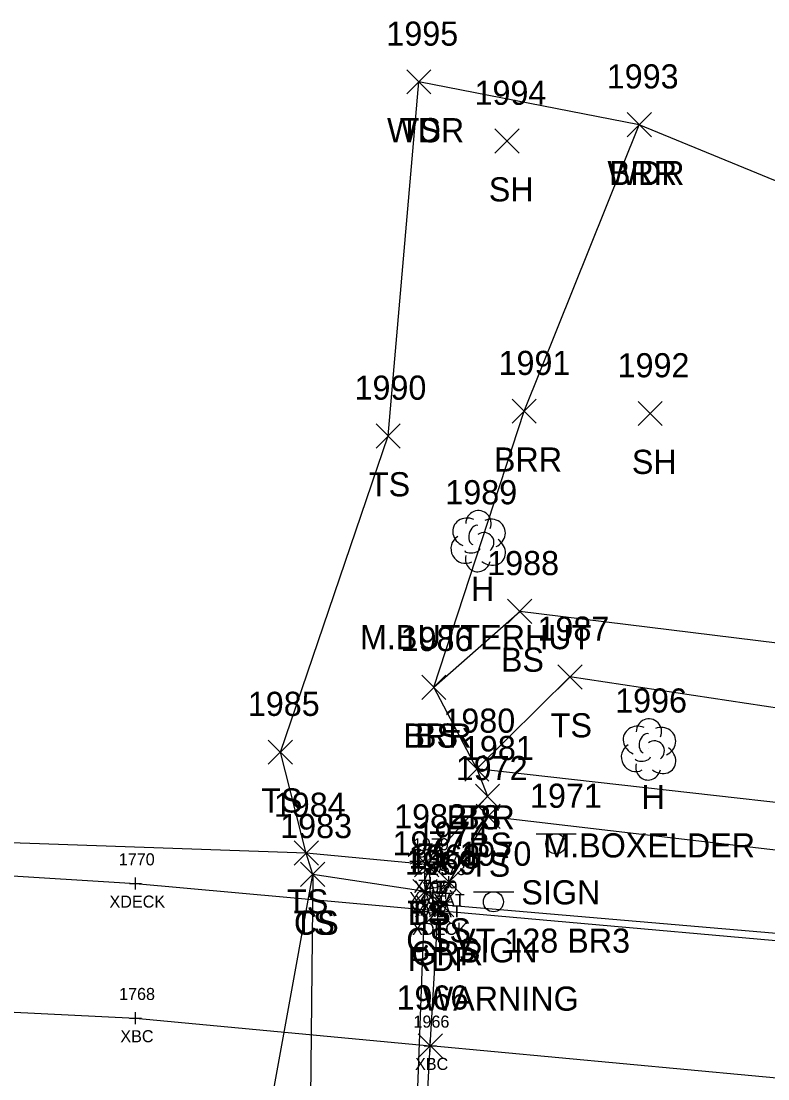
# Model space of a CAD drawing. Extents: x 1497084 to 1499861, y 734741 to 735567.
# Drawn here: x 1499561.5 to 1499623.4, y 735456.1 to 735543.7 of the extents above; entities that cross this region are included whole.
import ezdxf

# ---------------------------------------------------------------- set-up
doc = ezdxf.new("R2010")
doc.units = 0
for name, color, linetype in [('B_A', 7, 'Continuous'), ('B_I', 7, 'Continuous'), ('B_TIC', 7, 'Continuous'), ('BELB', 7, 'Continuous'), ('BSUBM', 7, 'Continuous'), ('L_A', 7, 'Continuous'), ('L_C', 7, 'Continuous'), ('L_I', 7, 'Continuous'), ('L_TIC', 7, 'Continuous'), ('LABL', 7, 'Continuous'), ('LAWA', 7, 'Continuous'), ('LELB', 7, 'Continuous'), ('LTD', 7, 'Continuous'), ('P_A', 7, 'Continuous'), ('P_I', 7, 'Continuous'), ('P_TIC', 7, 'Continuous'), ('PET', 7, 'Continuous'), ('PRC', 7, 'Continuous'), ('R_A', 7, 'Continuous'), ('R_I', 7, 'Continuous'), ('R_TIC', 7, 'Continuous'), ('RGR', 7, 'Continuous'), ('S_A', 7, 'Continuous'), ('S_C', 7, 'Continuous'), ('S_I', 7, 'Continuous'), ('SSGN', 7, 'Continuous')]:
    doc.layers.add(name, color=color, linetype=linetype)

msp = doc.modelspace()

# ---------------------------------------------------------------- linework, layer by layer
at = {"layer": 'B_TIC'}
for p, q in [((1499595.343, 735473.493), (1499595.419, 735473.493)), ((1499595.343, 735473.493), (1499595.419, 735473.493)), ((1499594.973, 735472.536), (1499595.048, 735472.536)), ((1499571.023, 735472.249), (1499571.099, 735472.249)), ((1499594.995, 735471.577), (1499595.071, 735471.577)), ((1499595.446, 735472.274), (1499595.522, 735472.274)), ((1499595.446, 735472.274), (1499595.522, 735472.274)), ((1499596.976, 735472.366), (1499597.051, 735472.366)), ((1499595.409, 735471.471), (1499595.484, 735471.471)), ((1499596.73, 735471.443), (1499596.806, 735471.443)), ((1499596.73, 735471.443), (1499596.806, 735471.443)), ((1499596.08, 735469.991), (1499596.156, 735469.991)), ((1499571.029, 735461.1), (1499571.104, 735461.1)), ((1499595.434, 735458.808), (1499595.509, 735458.808))]:
    msp.add_line(p, q, dxfattribs=at)
for points in [[(1499594.84, 735473.493), (1499595.84, 735473.493)], [(1499594.84, 735473.493), (1499595.84, 735473.493)], [(1499595.34, 735472.993), (1499595.34, 735473.993)], [(1499595.34, 735472.993), (1499595.34, 735473.993)], [(1499571.02, 735471.749), (1499571.02, 735472.749)], [(1499594.469, 735472.536), (1499595.469, 735472.536)], [(1499594.969, 735472.036), (1499594.969, 735473.036)], [(1499595.443, 735471.774), (1499595.443, 735472.774)], [(1499595.443, 735471.774), (1499595.443, 735472.774)], [(1499596.973, 735471.866), (1499596.973, 735472.866)], [(1499570.52, 735472.249), (1499571.52, 735472.249)], [(1499594.492, 735471.577), (1499595.492, 735471.577)], [(1499594.943, 735472.274), (1499595.943, 735472.274)], [(1499594.943, 735472.274), (1499595.943, 735472.274)], [(1499594.992, 735471.077), (1499594.992, 735472.077)], [(1499595.405, 735470.971), (1499595.405, 735471.971)], [(1499596.473, 735472.366), (1499597.473, 735472.366)], [(1499596.727, 735470.943), (1499596.727, 735471.943)], [(1499596.727, 735470.943), (1499596.727, 735471.943)], [(1499594.905, 735471.471), (1499595.905, 735471.471)], [(1499596.227, 735471.443), (1499597.227, 735471.443)], [(1499596.227, 735471.443), (1499597.227, 735471.443)], [(1499595.577, 735469.991), (1499596.577, 735469.991)], [(1499596.077, 735469.491), (1499596.077, 735470.491)], [(1499570.525, 735461.1), (1499571.525, 735461.1)], [(1499571.025, 735460.6), (1499571.025, 735461.6)], [(1499595.43, 735458.308), (1499595.43, 735459.308)], [(1499594.93, 735458.808), (1499595.93, 735458.808)]]:
    msp.add_lwpolyline(points, dxfattribs=at)
at = {"layer": 'BELB'}
for points in [[(1499513.907, 735475.175), (1499547.079, 735473.736), (1499571.02, 735472.249), (1499596.077, 735469.991)], [(1499547.013, 735462.289), (1499571.025, 735461.1), (1499595.43, 735458.808)]]:
    msp.add_lwpolyline(points, dxfattribs=at)
at = {"layer": 'BSUBM'}
for points in [[(1499594.157, 735445.59), (1499594.532, 735443.527), (1499592.76, 735443.901), (1499592.687, 735446.665), (1499594.054, 735446.482), (1499594.992, 735471.577), (1499594.969, 735472.536), (1499595.34, 735473.493)], [(1499596.727, 735471.443), (1499596.973, 735472.366), (1499595.443, 735472.274), (1499595.34, 735473.493)], [(1499596.727, 735471.443), (1499595.405, 735471.471), (1499595.443, 735472.274)]]:
    msp.add_lwpolyline(points, dxfattribs=at)
at = {"layer": 'L_TIC'}
for points in [[(1499593.485, 735537.631), (1499595.485, 735539.631)], [(1499595.485, 735537.631), (1499593.485, 735539.631)], [(1499593.485, 735537.631), (1499595.485, 735539.631)], [(1499595.485, 735537.631), (1499593.485, 735539.631)], [(1499611.735, 735534.087), (1499613.735, 735536.087)], [(1499613.735, 735534.087), (1499611.735, 735536.087)], [(1499611.735, 735534.087), (1499613.735, 735536.087)], [(1499613.735, 735534.087), (1499611.735, 735536.087)], [(1499600.786, 735532.733), (1499602.786, 735534.733)], [(1499602.786, 735532.733), (1499600.786, 735534.733)], [(1499602.208, 735510.359), (1499604.208, 735512.359)], [(1499604.208, 735510.359), (1499602.208, 735512.359)], [(1499612.635, 735510.165), (1499614.635, 735512.165)], [(1499614.635, 735510.165), (1499612.635, 735512.165)], [(1499590.936, 735508.31), (1499592.936, 735510.31)], [(1499592.936, 735508.31), (1499590.936, 735510.31)], [(1499601.834, 735493.783), (1499603.834, 735495.783)], [(1499603.834, 735493.783), (1499601.834, 735495.783)], [(1499601.834, 735493.783), (1499603.834, 735495.783)], [(1499603.834, 735493.783), (1499601.834, 735495.783)], [(1499605.997, 735488.35), (1499607.997, 735490.35)], [(1499607.997, 735488.35), (1499605.997, 735490.35)], [(1499594.722, 735487.498), (1499596.722, 735489.498)], [(1499596.722, 735487.498), (1499594.722, 735489.498)], [(1499594.722, 735487.498), (1499596.722, 735489.498)], [(1499596.722, 735487.498), (1499594.722, 735489.498)], [(1499582.013, 735482.125), (1499584.013, 735484.125)], [(1499584.013, 735482.125), (1499582.013, 735484.125)], [(1499598.291, 735480.733), (1499600.291, 735482.733)], [(1499600.291, 735480.733), (1499598.291, 735482.733)], [(1499598.291, 735480.733), (1499600.291, 735482.733)], [(1499600.291, 735480.733), (1499598.291, 735482.733)], [(1499599.174, 735478.467), (1499601.174, 735480.467)], [(1499601.174, 735478.467), (1499599.174, 735480.467)], [(1499599.229, 735476.808), (1499601.229, 735478.808)], [(1499601.229, 735476.808), (1499599.229, 735478.808)], [(1499584.162, 735473.769), (1499586.162, 735475.769)], [(1499586.162, 735473.769), (1499584.162, 735475.769)], [(1499584.162, 735473.769), (1499586.162, 735475.769)], [(1499586.162, 735473.769), (1499584.162, 735475.769)], [(1499594.127, 735472.813), (1499596.127, 735474.813)], [(1499596.127, 735472.813), (1499594.127, 735474.813)], [(1499594.127, 735472.813), (1499596.127, 735474.813)], [(1499596.127, 735472.813), (1499594.127, 735474.813)], [(1499584.691, 735472.006), (1499586.691, 735474.006)], [(1499586.691, 735472.006), (1499584.691, 735474.006)], [(1499584.691, 735472.006), (1499586.691, 735474.006)], [(1499586.691, 735472.006), (1499584.691, 735474.006)], [(1499595.973, 735471.366), (1499597.973, 735473.366)], [(1499597.973, 735471.366), (1499595.973, 735473.366)], [(1499593.992, 735470.577), (1499595.992, 735472.577)], [(1499595.992, 735470.577), (1499593.992, 735472.577)]]:
    msp.add_lwpolyline(points, dxfattribs=at)
at = {"layer": 'LABL'}
msp.add_lwpolyline([(1499689.554, 735474.192), (1499666.752, 735480.946), (1499644.867, 735476.617), (1499599.291, 735481.733), (1499595.722, 735488.498), (1499603.208, 735511.359), (1499612.735, 735535.087)], dxfattribs=at)
at = {"layer": 'LAWA'}
msp.add_lwpolyline([(1499788.738, 735496.153), (1499778.307, 735474.671), (1499770.599, 735459.37), (1499768.79, 735460.678), (1499758.938, 735469.149), (1499746.531, 735488.898), (1499729.211, 735490.085), (1499697.802, 735511.882), (1499637.791, 735524.775), (1499612.735, 735535.087), (1499594.485, 735538.631)], dxfattribs=at)
at = {"layer": 'LELB'}
for points in [[(1499570.905, 735379.498), (1499570.867, 735411.967), (1499572.156, 735424.754), (1499577.616, 735446.541), (1499581.073, 735447.466), (1499585.691, 735473.006), (1499585.162, 735474.769), (1499583.013, 735483.125), (1499591.936, 735509.31), (1499594.485, 735538.631)], [(1499595.722, 735488.498), (1499602.834, 735494.783)], [(1499675.288, 735482.485), (1499642.088, 735489.947), (1499602.834, 735494.783)], [(1499606.997, 735489.35), (1499599.291, 735481.733)], [(1499675.288, 735482.485), (1499642.096, 735484.057), (1499606.997, 735489.35)], [(1499599.291, 735481.733), (1499600.174, 735479.467), (1499595.127, 735473.813)], [(1499770.599, 735459.37), (1499767.316, 735451.404), (1499753.266, 735453.514), (1499723.327, 735458.194), (1499688.043, 735465.791), (1499662.005, 735476.729), (1499649.942, 735471.977), (1499600.229, 735477.808), (1499596.973, 735472.366)], [(1499585.162, 735474.769), (1499521.999, 735476.976)], [(1499595.127, 735473.813), (1499585.162, 735474.769)], [(1499585.691, 735473.006), (1499585.417, 735446.564)], [(1499594.992, 735471.577), (1499585.691, 735473.006)]]:
    msp.add_lwpolyline(points, dxfattribs=at)
at = {"layer": 'LTD'}
for p, q in [((1499599.376, 735500.65), (1499599.376, 735500.65)), ((1499599.376, 735500.65), (1499599.376, 735500.65)), ((1499613.487, 735483.403), (1499613.487, 735483.403)), ((1499613.487, 735483.403), (1499613.487, 735483.403))]:
    msp.add_line(p, q, dxfattribs=at)
for centre in [(1499599.423, 735502.084), (1499613.534, 735484.837)]:
    msp.add_arc(centre, 1.047, 335.52715, 180.95627, dxfattribs=at)
for centre, major_axis, ratio, start_param, end_param in [((1499598.584, 735501.316), (1.21, -0.512), 0.895232, 1.570796, 4.712389), ((1499600.418, 735501.233), (-1.141, -0.483), 0.949671, 1.570796, 4.712389), ((1499599.168, 735501.108), (-0.208, -0.792), 0.645439, 3.141593, 6.283185), ((1499599.876, 735500.483), (-0.5, 0.667), 0.989748, 3.141593, 6.283185), ((1499598.293, 735499.941), (0.584, -1.042), 0.959034, 3.141593, 6.283185), ((1499600.376, 735499.817), (-1.09, 0.792), 0.841452, 1.570796, 4.712389), ((1499598.918, 735499.9), (-0.625, -0.083), 0.423636, 0, 3.141593), ((1499599.376, 735499.15), (0.265, 1.061), 0.942809, 1.570796, 4.712389), ((1499612.695, 735484.07), (1.21, -0.512), 0.895232, 1.570796, 4.712389), ((1499613.279, 735483.862), (-0.208, -0.792), 0.645439, 3.141593, 6.283185), ((1499614.529, 735483.987), (-1.141, -0.483), 0.949671, 1.570796, 4.712389), ((1499613.987, 735483.237), (-0.5, 0.667), 0.989748, 3.141593, 6.283185), ((1499612.404, 735482.695), (0.584, -1.042), 0.959034, 3.141593, 6.283185), ((1499614.487, 735482.57), (-1.09, 0.792), 0.841452, 1.570796, 4.712389), ((1499613.487, 735481.903), (0.265, 1.061), 0.942809, 1.570796, 4.712389), ((1499613.029, 735482.653), (-0.625, -0.083), 0.423636, 0, 3.141593)]:
    msp.add_ellipse(centre, major_axis=major_axis, ratio=ratio, start_param=start_param, end_param=end_param, dxfattribs=at)
at = {"layer": 'P_TIC'}
for points in [[(1499595.077, 735468.991), (1499597.077, 735470.991)], [(1499597.077, 735468.991), (1499595.077, 735470.991)], [(1499595.077, 735468.991), (1499597.077, 735470.991)], [(1499597.077, 735468.991), (1499595.077, 735470.991)], [(1499594.43, 735457.808), (1499596.43, 735459.808)], [(1499596.43, 735457.808), (1499594.43, 735459.808)], [(1499594.43, 735457.808), (1499596.43, 735459.808)], [(1499596.43, 735457.808), (1499594.43, 735459.808)]]:
    msp.add_lwpolyline(points, dxfattribs=at)
at = {"layer": 'PET'}
for points in [[(1499842.353, 735402.928), (1499782.679, 735418.081), (1499750.409, 735424.994), (1499714.978, 735432.412), (1499683.044, 735438.059), (1499645.695, 735442.942), (1499594.849, 735447.923), (1499595.43, 735458.808), (1499596.077, 735469.991)], [(1499846.488, 735425.23), (1499785.866, 735440.032), (1499753.42, 735446.608), (1499720.619, 735453.442), (1499687.533, 735458.833), (1499650.762, 735464.505), (1499635.869, 735466.456), (1499596.077, 735469.991)]]:
    msp.add_lwpolyline(points, dxfattribs=at)
at = {"layer": 'PRC'}
msp.add_lwpolyline([(1499843.886, 735414.074), (1499783.911, 735429.159), (1499752.36, 735435.285), (1499717.649, 735442.891), (1499685.251, 735447.999), (1499648.687, 735453.839), (1499595.43, 735458.808)], dxfattribs=at)
at = {"layer": 'R_TIC'}
for points in [[(1499595.371, 735469.478), (1499597.371, 735471.478)], [(1499597.371, 735469.478), (1499595.371, 735471.478)]]:
    msp.add_lwpolyline(points, dxfattribs=at)
at = {"layer": 'RGR'}
msp.add_lwpolyline([(1499661.063, 735469.133), (1499651.881, 735467.189), (1499636.029, 735467.086), (1499596.371, 735470.478)], dxfattribs=at)
at = {"layer": 'SSGN'}
for p, q in [((1499604.188, 735476.37), (1499607.521, 735476.37)), ((1499605.834, 735475.536), (1499605.834, 735475.536)), ((1499599.008, 735471.568), (1499602.341, 735471.568)), ((1499600.655, 735470.734), (1499600.655, 735470.734))]:
    msp.add_line(p, q, dxfattribs=at)
for centre in [(1499605.834, 735475.536), (1499600.655, 735470.734)]:
    msp.add_circle(centre, 0.833, dxfattribs=at)

# ---------------------------------------------------------------- texts
at = {"layer": 'B_A'}
for s, p in [('XAT', (1499594.045, 735471.493)), ('XAB', (1499594.06, 735471.493)), ('XAB', (1499593.69, 735470.536)), ('XDECK', (1499568.862, 735470.249)), ('XAT', (1499594.147, 735470.274)), ('XAT', (1499594.147, 735470.274)), ('XAT', (1499595.677, 735470.366)), ('XAB', (1499593.712, 735469.577)), ('XAT', (1499594.11, 735469.471)), ('XAT', (1499595.432, 735469.443)), ('XAT', (1499595.432, 735469.443)), ('XDECK', (1499593.92, 735467.991)), ('XBC', (1499569.762, 735459.1)), ('XBC', (1499594.167, 735456.808))]:
    msp.add_text(s, height=1, dxfattribs=at).set_placement(p)
at = {"layer": 'B_I'}
for s, p in [('1979', (1499593.99, 735474.993)), ('1979', (1499593.99, 735474.993)), ('1978', (1499593.623, 735474.036)), ('1770', (1499569.63, 735473.749)), ('1976', (1499594.069, 735473.774)), ('1976', (1499594.069, 735473.774)), ('1974', (1499595.626, 735473.866)), ('1977', (1499593.645, 735473.077)), ('1975', (1499594.059, 735472.971)), ('1973', (1499595.38, 735472.943)), ('1973', (1499595.38, 735472.943)), ('1969', (1499594.703, 735471.491)), ('1768', (1499569.655, 735462.6)), ('1966', (1499594.033, 735460.308))]:
    msp.add_text(s, height=1, dxfattribs=at).set_placement(p)
at = {"layer": 'L_A'}
for s, p in [('WDR', (1499591.848, 735533.631)), ('TS', (1499592.895, 735533.631)), ('WDR', (1499610.097, 735530.087)), ('BRR', (1499610.223, 735530.087)), ('SH', (1499600.274, 735528.733)), ('BRR', (1499600.696, 735506.359)), ('SH', (1499612.123, 735506.165)), ('TS', (1499590.345, 735504.31)), ('H', (1499598.809, 735495.65)), ('BS', (1499601.275, 735489.783)), ('BS', (1499601.275, 735489.783)), ('BS', (1499594.163, 735483.498)), ('TS', (1499605.406, 735484.35)), ('BRR', (1499593.21, 735483.498)), ('H', (1499612.92, 735478.403)), ('TS', (1499581.422, 735478.125)), ('BRR', (1499596.78, 735476.733)), ('BS', (1499597.732, 735476.733)), ('BS', (1499598.615, 735474.467)), ('TS', (1499598.638, 735472.808)), ('TS', (1499583.571, 735469.769)), ('TS', (1499583.571, 735469.769)), ('TS', (1499593.536, 735468.813)), ('BS', (1499593.568, 735468.813)), ('TS', (1499584.101, 735468.006)), ('CS', (1499584.132, 735468.006)), ('TS', (1499595.382, 735467.366)), ('CS', (1499593.433, 735466.577))]:
    msp.add_text(s, height=2, dxfattribs=at).set_placement(p)
at = {"layer": 'L_C'}
for s, p in [('M.BUTTERHUT', (1499589.604, 735491.65)), ('M.BOXELDER', (1499604.786, 735474.403))]:
    msp.add_text(s, height=2, dxfattribs=at).set_placement(p)
at = {"layer": 'L_I'}
for s, p in [('1995', (1499591.792, 735541.631)), ('1995', (1499591.792, 735541.631)), ('1993', (1499610.042, 735538.087)), ('1993', (1499610.042, 735538.087)), ('1994', (1499599.093, 735536.733)), ('1991', (1499601.082, 735514.359)), ('1992', (1499610.942, 735514.165)), ('1990', (1499589.156, 735512.31)), ('1989', (1499596.675, 735503.65)), ('1988', (1499600.141, 735497.783)), ('1988', (1499600.141, 735497.783)), ('1987', (1499604.304, 735492.35)), ('1986', (1499592.974, 735491.498)), ('1986', (1499592.974, 735491.498)), ('1985', (1499580.32, 735486.125)), ('1996', (1499610.739, 735486.403)), ('1980', (1499596.512, 735484.733)), ('1980', (1499596.512, 735484.733)), ('1981', (1499598.048, 735482.467)), ('1972', (1499597.536, 735480.808)), ('1984', (1499582.469, 735477.769)), ('1984', (1499582.469, 735477.769)), ('1982', (1499592.434, 735476.813)), ('1982', (1499592.434, 735476.813)), ('1983', (1499582.998, 735476.006)), ('1983', (1499582.998, 735476.006)), ('1974', (1499594.28, 735475.366)), ('1977', (1499592.299, 735474.577))]:
    msp.add_text(s, height=2, dxfattribs=at).set_placement(p)
at = {"layer": 'P_A'}
msp.add_text('RDP', height=2, dxfattribs=at).set_placement((1499593.565, 735464.991))
msp.add_text('RDP', height=2, dxfattribs=at).set_placement((1499593.565, 735464.991))
at = {"layer": 'P_I'}
for s, p in [('1969', (1499593.329, 735472.991)), ('1969', (1499593.329, 735472.991)), ('1966', (1499592.635, 735461.808)), ('1966', (1499592.635, 735461.808))]:
    msp.add_text(s, height=2, dxfattribs=at).set_placement(p)
at = {"layer": 'R_A'}
msp.add_text('GRR', height=2, dxfattribs=at).set_placement((1499593.859, 735465.478))
at = {"layer": 'R_I'}
msp.add_text('1968', height=2, dxfattribs=at).set_placement((1499593.631, 735473.478))
at = {"layer": 'S_A'}
for p in [(1499602.972, 735470.516), (1499597.792, 735465.714)]:
    msp.add_text('SIGN', height=2, dxfattribs=at).set_placement(p)
at = {"layer": 'S_C'}
for s, p in [('VT 128 BR3', (1499597.405, 735466.516)), ('WARNING', (1499594.8, 735461.714))]:
    msp.add_text(s, height=2, dxfattribs=at).set_placement(p)
at = {"layer": 'S_I'}
for s, p in [('1971', (1499603.689, 735478.516)), ('1970', (1499597.855, 735473.714))]:
    msp.add_text(s, height=2, dxfattribs=at).set_placement(p)

doc.saveas('drawing.dxf')
